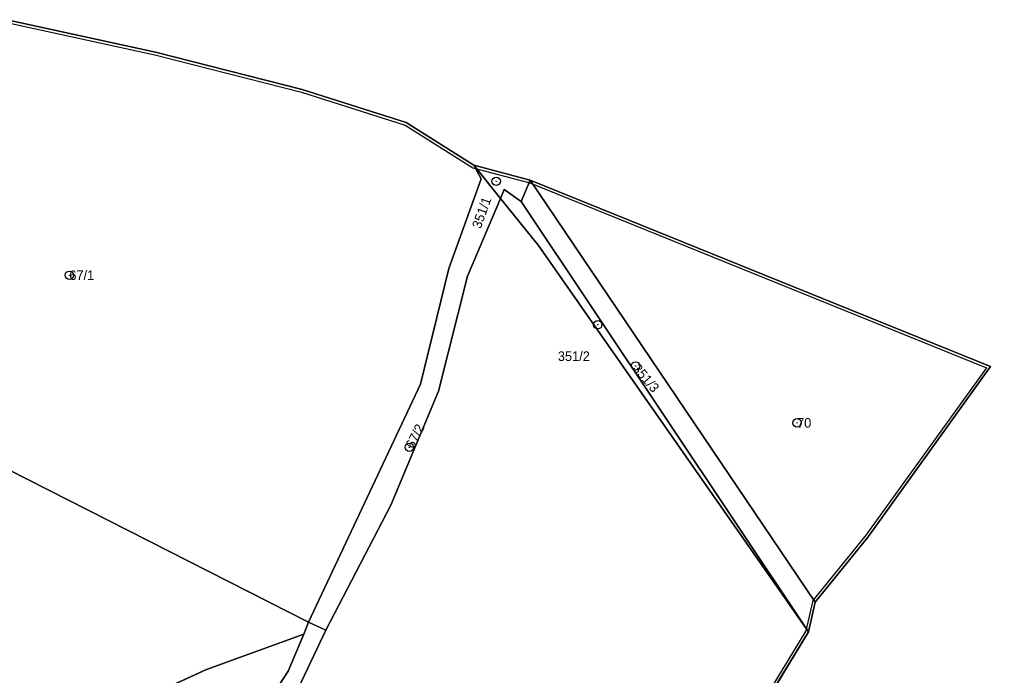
# Model space of a CAD drawing. Extents: x -652854 to -650068, y -1097661 to -1095417.
# Drawn here: x -650241 to -650068.3, y -1095838.2 to -1095721.6 of the extents above; entities that cross this region are included whole.
import ezdxf

# ---------------------------------------------------------------- set-up
doc = ezdxf.new("R2010")
doc.units = 0
for name, color, linetype in [('Definiční body parcel', 7, 'Continuous'), ('Hranice kat_ území', 7, 'Continuous'), ('Hranice obcí', 7, 'Continuous'), ('Hranice parcel', 7, 'Continuous'), ('Obvody jako plochy', 7, 'Continuous'), ('Ostatní hranice', 7, 'Continuous'), ('Parcelní čísla', 7, 'Continuous'), ('Prvky pro prodl_ par_ č_', 7, 'Continuous')]:
    doc.layers.add(name, color=color, linetype=linetype)

msp = doc.modelspace()

# ---------------------------------------------------------------- linework, layer by layer
at = {"layer": 'Definiční body parcel'}
for centre, radius in [((-650156.22, -1095750.37), 0.75), ((-650156.22, -1095750.37), 0.0327), ((-650232.09, -1095767.06), 0.75), ((-650232.09, -1095767.06), 0.0327), ((-650138.17, -1095775.85), 0.75), ((-650138.17, -1095775.85), 0.0327), ((-650131.43, -1095783.18), 0.75), ((-650131.43, -1095783.18), 0.0327), ((-650102.74, -1095793.29), 0.75), ((-650102.74, -1095793.29), 0.0327), ((-650171.64, -1095797.64), 0.75), ((-650171.64, -1095797.64), 0.0327)]:
    msp.add_circle(centre, radius, dxfattribs=at)
at = {"layer": 'Hranice kat_ území'}
for p, q in [((-650068.34, -1095783.27), (-650090.1, -1095813.55)), ((-650090.1, -1095813.55), (-650099.53, -1095825.15)), ((-650099.53, -1095825.15), (-650100.71, -1095830.46)), ((-650100.71, -1095830.46), (-650154.36, -1095918.36))]:
    msp.add_line(p, q, dxfattribs=at)
at = {"layer": 'Hranice obcí'}
for p, q in [((-650243.45, -1095721.6), (-650216.76, -1095727.42)), ((-650216.76, -1095727.42), (-650190.73, -1095734.05)), ((-650190.73, -1095734.05), (-650172.22, -1095739.93)), ((-650172.22, -1095739.93), (-650160.2, -1095747.49)), ((-650160.2, -1095747.49), (-650150.15, -1095750.14)), ((-650150.15, -1095750.14), (-650068.34, -1095783.27))]:
    msp.add_line(p, q, dxfattribs=at)
at = {"layer": 'Hranice parcel'}
for p, q in [((-650155.45, -1095753.4), (-650160.2, -1095747.49)), ((-650158.87, -1095749.95), (-650160.2, -1095747.49)), ((-650164.66, -1095765.89), (-650158.87, -1095749.95)), ((-650150.15, -1095750.14), (-650151.77, -1095753.94)), ((-650099.53, -1095825.15), (-650150.15, -1095750.14)), ((-650154.8, -1095751.84), (-650155.45, -1095753.4)), ((-650151.77, -1095753.94), (-650154.8, -1095751.84)), ((-650155.45, -1095753.4), (-650161.33, -1095767.24)), ((-650148.69, -1095761.8), (-650155.45, -1095753.4)), ((-650151.77, -1095753.94), (-650100.71, -1095830.46)), ((-650100.71, -1095830.46), (-650148.69, -1095761.8)), ((-650169.66, -1095786.41), (-650164.66, -1095765.89)), ((-650161.33, -1095767.24), (-650166.46, -1095787.68)), ((-650189.59, -1095828.72), (-650296.41, -1095774.45)), ((-650189.59, -1095828.72), (-650169.66, -1095786.41)), ((-650166.46, -1095787.68), (-650174.93, -1095807.91)), ((-650174.93, -1095807.91), (-650186.5, -1095830.15)), ((-650190.42, -1095830.87), (-650189.59, -1095828.72)), ((-650189.59, -1095828.72), (-650186.5, -1095830.15)), ((-650207.69, -1095837.1), (-650190.42, -1095830.87)), ((-650190.42, -1095830.87), (-650193.21, -1095837.43)), ((-650186.5, -1095830.15), (-650190.83, -1095839.27)), ((-650228.23, -1095846.5), (-650207.69, -1095837.1)), ((-650193.21, -1095837.43), (-650210.57, -1095864.06))]:
    msp.add_line(p, q, dxfattribs=at)
at = {"layer": 'Obvody jako plochy'}
for points in [[(-650216.76, -1095727.42), (-650243.45, -1095721.6), (-650296.41, -1095774.45), (-650189.59, -1095828.72), (-650169.66, -1095786.41), (-650164.66, -1095765.89), (-650158.87, -1095749.95), (-650160.2, -1095747.49), (-650172.22, -1095739.93), (-650190.73, -1095734.05)], [(-650189.59, -1095828.72), (-650186.5, -1095830.15), (-650174.93, -1095807.91), (-650166.46, -1095787.68), (-650161.33, -1095767.24), (-650155.45, -1095753.4), (-650160.2, -1095747.49), (-650158.87, -1095749.95), (-650164.66, -1095765.89), (-650169.66, -1095786.41)], [(-650160.2, -1095747.49), (-650155.45, -1095753.4), (-650154.8, -1095751.84), (-650151.77, -1095753.94), (-650150.15, -1095750.14)], [(-650150.15, -1095750.14), (-650151.77, -1095753.94), (-650100.71, -1095830.46), (-650099.53, -1095825.15)], [(-650150.15, -1095750.14), (-650099.53, -1095825.15), (-650090.1, -1095813.55), (-650068.34, -1095783.27)], [(-650151.77, -1095753.94), (-650154.8, -1095751.84), (-650155.45, -1095753.4), (-650148.69, -1095761.8), (-650100.71, -1095830.46)], [(-650238.47, -1095909.71), (-650211.58, -1095942.62), (-650187.6, -1095963.64), (-650185.74, -1095959.74), (-650175.6, -1095938.45), (-650154.36, -1095918.36), (-650100.71, -1095830.46), (-650148.69, -1095761.8), (-650155.45, -1095753.4), (-650161.33, -1095767.24), (-650166.46, -1095787.68), (-650174.93, -1095807.91), (-650186.5, -1095830.15), (-650190.83, -1095839.27), (-650208.29, -1095868.16), (-650219.19, -1095882.79)], [(-650318.03, -1095792.3), (-650332.5, -1095771.86), (-650380.34, -1095795.33), (-650384.29, -1095789.19), (-650390.71, -1095795.38), (-650404.41, -1095793.36), (-650412.7, -1095808.67), (-650415.8, -1095834.87), (-650409.55, -1095851.54), (-650399.87, -1095862.15), (-650389.75, -1095872.8), (-650374.95, -1095883.69), (-650363.46, -1095882.3), (-650295.45, -1095857.4), (-650246.6, -1095852.26), (-650228.23, -1095846.5), (-650207.69, -1095837.1), (-650190.42, -1095830.87), (-650189.59, -1095828.72), (-650296.41, -1095774.45)], [(-650246.6, -1095852.26), (-650245.43, -1095854.13), (-650210.57, -1095864.06), (-650193.21, -1095837.43), (-650190.42, -1095830.87), (-650207.69, -1095837.1), (-650228.23, -1095846.5)]]:
    msp.add_lwpolyline(points, close=True, dxfattribs=at)
msp.add_lwpolyline([(-650190.83, -1095839.27), (-650186.5, -1095830.15), (-650189.59, -1095828.72), (-650190.42, -1095830.87), (-650193.21, -1095837.43), (-650210.57, -1095864.06)], dxfattribs=at)
at = {"layer": 'Ostatní hranice'}
for p, q in [((-650243.52, -1095722.11), (-650216.87, -1095727.92)), ((-650216.87, -1095727.92), (-650190.83, -1095734.55)), ((-650190.83, -1095734.55), (-650172.42, -1095740.4)), ((-650172.42, -1095740.4), (-650160.39, -1095747.97)), ((-650160.39, -1095747.97), (-650150.24, -1095750.64)), ((-650150.24, -1095750.64), (-650069.09, -1095783.51)), ((-650069.09, -1095783.51), (-650090.51, -1095813.25)), ((-650090.51, -1095813.25), (-650099.95, -1095824.85)), ((-650099.95, -1095824.85), (-650101.17, -1095830.24)), ((-650101.17, -1095830.24), (-650154.74, -1095918.01))]:
    msp.add_line(p, q, dxfattribs=at)

# ---------------------------------------------------------------- texts
at = {"layer": 'Parcelní čísla'}
for s, height, p in [('351/1', 0.1, (-650156.22, -1095750.42)), ('67/1', 1.7, (-650232.09, -1095767.91)), ('351/2', 0.1, (-650138.17, -1095775.9)), ('70', 1.7, (-650102.74, -1095794.14))]:
    msp.add_text(s, height=height, dxfattribs=at).set_placement(p)
for s, rotation, p in [('351/3', 310.563, (-650132.076, -1095783.733)), ('67/2', 63.27, (-650170.881, -1095798.022))]:
    msp.add_text(s, height=1.7, rotation=rotation, dxfattribs=at).set_placement(p)
at = {"layer": 'Prvky pro prodl_ par_ č_'}
msp.add_text('351/1', height=1.7, rotation=70.362, dxfattribs=at).set_placement((-650158.976, -1095758.91))
msp.add_text('351/2', height=1.7, dxfattribs=at).set_placement((-650145.258, -1095782.3))

doc.saveas('drawing.dxf')
